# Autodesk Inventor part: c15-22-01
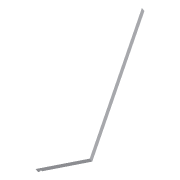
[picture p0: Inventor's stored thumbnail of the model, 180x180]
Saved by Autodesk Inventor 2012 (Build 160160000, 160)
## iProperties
Created: 2011-02
Part Number: c15-22-01
Material: Default
Document SubType Name: Modeling
Designer: Beta-8540w
Density: 1 g/cm^3
Author: Beta-8540w
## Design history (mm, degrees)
derived "c15-13.ipt" dims "d2" = 12.7, "d3" = 0, "d4" = 6.35, "d6" = 3.302, "d7" = 0, "drawer_depth" = 514.35, "drawer_side_height" = 177.8, "bottom_thickness" = 6.35
body "Solid1"
feature "Solid1::c15-13.ipt" dims "d2" = 12.7, "d3" = 0, "d4" = 6.35, "d6" = 3.302, "d7" = 0, "drawer_depth" = 514.35, "drawer_side_height" = 177.8, "bottom_thickness" = 6.35, "ScaleForDerivedMember" = 10
tag "TaggingFeature1"
